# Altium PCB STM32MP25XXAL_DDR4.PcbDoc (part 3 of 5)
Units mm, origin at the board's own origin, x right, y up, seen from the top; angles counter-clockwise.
Board outline 125 x 95 mm, 6 copper layers (Top Layer, Signal Layer 1, Signal Layer 2, Signal Layer 3, Signal Layer 4, Bottom Layer), stack 1.403 mm thick; 220 components, 316 nets, 1103 pads, 939 vias.
Unrouted connection lines stored in the file: 5.
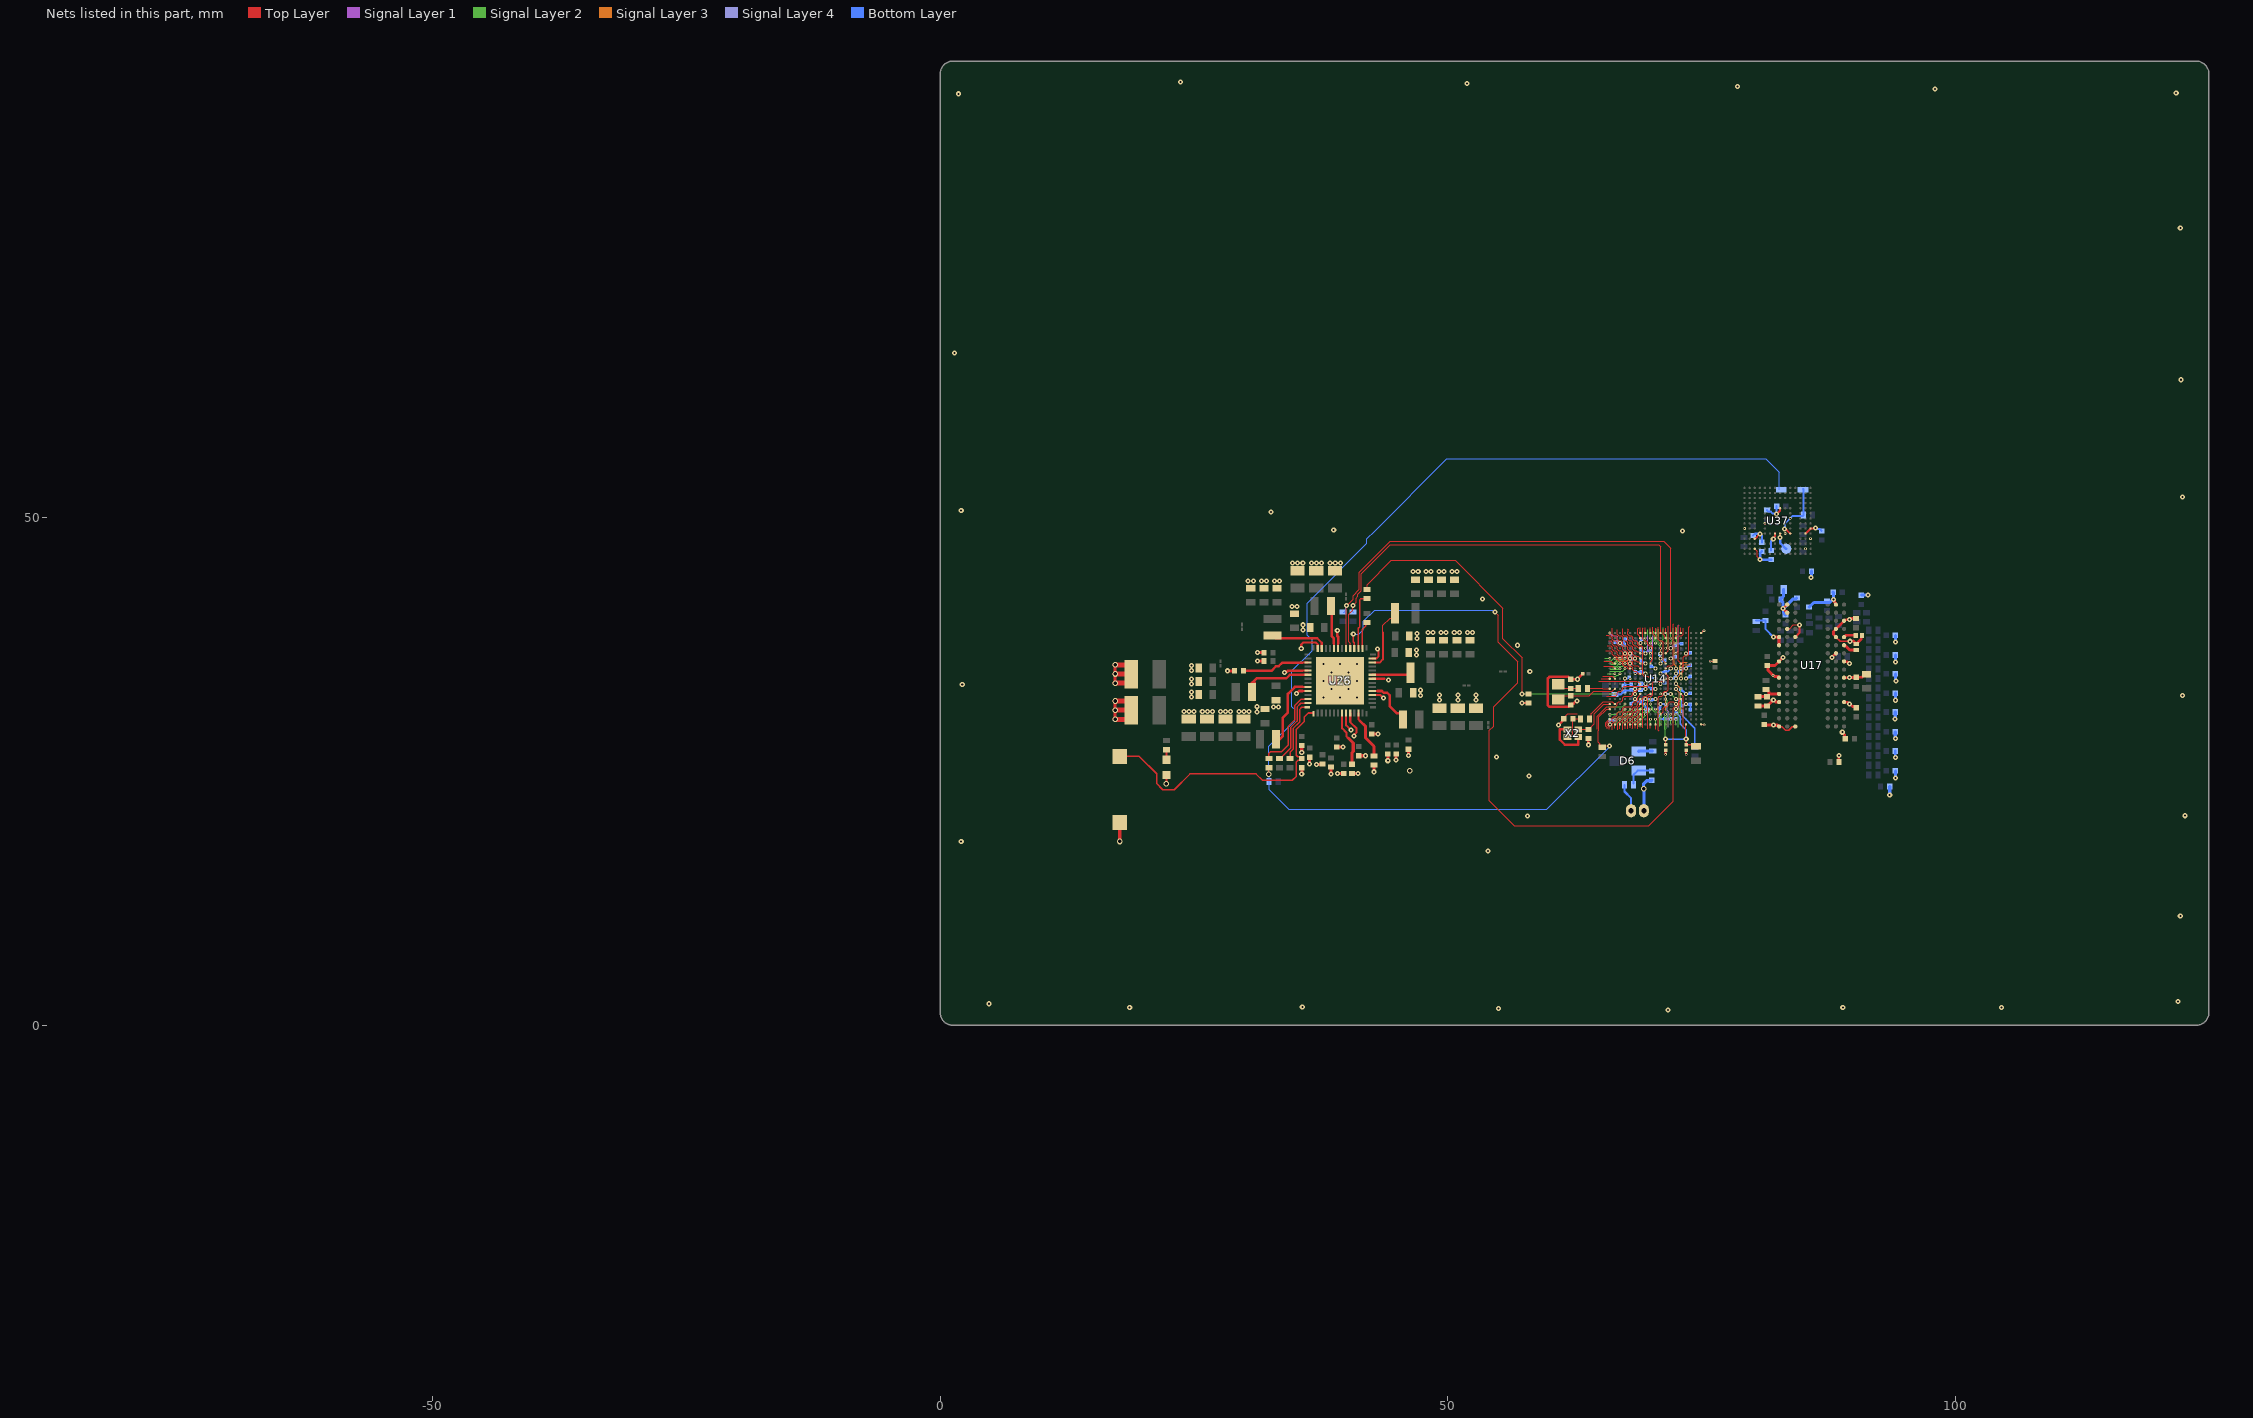
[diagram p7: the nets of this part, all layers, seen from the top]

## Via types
v1: diameter 0.5, hole 0.2, Top Layer to Bottom Layer, 292 vias
v2: diameter 0.26, hole 0.1, Top Layer to Signal Layer 1, 266 vias
v3: diameter 0.26, hole 0.1, Signal Layer 1 to Signal Layer 2, 143 vias
v4: diameter 0.4, hole 0.2, Signal Layer 1 to Signal Layer 4, 101 vias
v5: diameter 0.26, hole 0.1, Signal Layer 4 to Bottom Layer, 81 vias
v6: diameter 0.55, hole 0.35, Top Layer to Bottom Layer, 55 vias
v7: diameter 0.5, hole 0.2, Signal Layer 1 to Signal Layer 4, 1 vias

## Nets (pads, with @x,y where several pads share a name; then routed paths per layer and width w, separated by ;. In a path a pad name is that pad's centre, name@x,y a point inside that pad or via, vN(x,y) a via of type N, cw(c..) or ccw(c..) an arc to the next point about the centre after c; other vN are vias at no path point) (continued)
GND: B2.1 C1.1 C2.1 C3.1 C4.1 C5.1 C9.1 C14.1 C15.1 C16.1 C17.1 C18.2 C19.1 C20.1 C21.1 C22.1 C23.1 C24.1 C26.1 C27.1 C28.1 C29.1 C30.1 C32.1 C33.1 C34.1 C35.1 C36.1 C37.1 C38.1 C39.1 C40.1 C41.1 C42.2 C43.1 C70.1 C79.1 C81.2 C82.1 C86.2 C87.1 C90.1 C91.2 C92.2 C94.1 C104.1 C105.1 C106.1 C112.1 C117.1 C118.1 C128.1 C130.1 C141.2 C142.2 C144.1 C145.1 C146.1 C152.1 C153.1 C154.1 C155.1 C156.1 C157.1 C160.1 C172.1 C175.2 C177.2 C178.1 C179.1 C181.1 C183.1 C184.1 C186.1 C187.1 C188.1 C189.1 C190.2 C191.2 C192.2 C193.1 C194.1 C195.2 C196.1 C197.1 C199.1 C200.1 C201.1 C202.1 C203.2 C204.1 C205.1 C206.1 C207.1 C208.2 C209.1 C210.1 C211.2 C212.1 C213.1 C214.1 C215.1 C217.2 C218.1 C219.1 C220.1 C225.1 C226.1 C234.1 C235.1 C236.1 C237.1 C238.1 C239.1 C240.1 C244.1 C246.1 C248.1 C250.1 C251.1 C252.1 C253.1 C254.1 C255.1 C256.1 C257.1 C258.1 C259.1 C260.1 C261.1 C265.1 C266.1 C283.1 C284.2 C287.1 C289.1 C299.1 C300.1 C304.2 C306.2 C307.2 CN12.2 LD11.2 R57.1 R112.1 R113.1 R118.1 R176.1 R179.1 U14.A1 U14.A19 U14.C3 U14.C7 U14.D13 U14.E8 U14.E16 U14.F6 U14.F11 U14.F13 U14.G8 U14.G11 U14.H10 U14.H13 U14.H16 U14.J6 U14.J8 U14.J11 U14.J14 U14.K4 U14.K5 U14.K10 U14.K13 U14.K16 U14.L8 U14.L11 U14.M6 U14.M10 U14.N11 U14.N13 U14.N16 U14.P6 U14.P8 U14.P10 U14.P14 U14.R11 U14.R16 U14.R18 U14.U1 U14.W1 U14.W19 U17.A2 U17.A8 U17.B2 U17.C9 U17.D2 U17.D8 U17.E1 U17.E3 U17.E8 U17.F1 U17.G8 U17.H1 U17.H9 U17.K1 U17.K9 U17.N1 U17.N9 U17.T1 U17.T3 U26.9 U26.10 U26.18 U26.22 U26.27 U26.36 U26.41 U26.47 U26.52 U26.57 U37.A6 U37.C4 U37.E7 U37.G5 U37.H10 U37.J5 U37.K8 U37.N2 U37.N5 U37.P4 U37.P6 X2.2 X2.4 | length 159.1
  Top Layer w0.075: v2@75.225,38.9 v2@75.275,38.9 ; R112.1@76.35,35.875 76.4,35.875 R112.1@76.425,35.85
  Top Layer w0.09: v2(85.25,46.95) 85.25,46.948 U37.N2@85.251,46.947
  Top Layer w0.1: v1@60.815,29.688 v1(60.901,29.602) ; C92.2@61.431,30.192 61.431,30.294 61.836,30.7 62.761,30.7 ; v1@62.677,34.095 v1@62.709,34.095 ; U14.W19@74.975,29.65 v2@75.3,29.65 ; U14.A19@74.975,38.65 v2@75.225,38.9 ; v2(75.87,35.875) R112.1@76.35,35.875 ; U17.D2@83.45,39.05 83.492,39.092 83.703,39.092 84.06,39.45 v1(84.65,39.45)
  Top Layer w0.15: v2(79.25,48.95) v2(79.25,48.95) U37.A6@79.251,48.947 ; U17.T1@82.65,29.45 82.675,29.425 82.945,29.425 83.295,29.075 83.605,29.075 83.955,29.425 84.225,29.425 U17.T3@84.25,29.45 ; v2(85.75,47.95) 85.75,47.948 U37.P4@85.751,47.947
  Top Layer w0.18: U17.E8@88.25,38.25 88.66,37.84 89.212,37.84 89.217,37.835 v1(89.65,37.835) 89.665,37.85 89.951,37.85
  Top Layer w0.2: v6@22.284,23.784 LD11.2@22.284,24.661 ; U26.27@42.568,36.139 42.977,36.139 43.168,36.33 43.168,37.049 v1@43.214,37.095 ; v1(43.068,37.069) v1@43.125,37.012 ; v1(57.325,31.75) 57.925,31.75 C33.1@57.95,31.725 ; v2(71.475,26.7) C214.1@71.475,27.1 ; v2(73.5,26.7) C260.1@73.5,27.1 ; U37.C4@80.25,47.95 80.256,47.956 80.291,47.956 v1(80.75,48.415) ; v2(81.25,49.45) v2(81.25,49.45) U37.E7@81.251,49.447 ; v1(82.076,47.922) 82.076,48.01 82.251,48.185 U37.G5@82.251,48.447 ; v1(82.401,50.372) 82.751,50.722 U37.H10@82.751,50.947 ; v2(83.25,48.45) 83.251,48.449 U37.J5@83.251,48.447 ; v2(83.75,49.95) v2(83.75,49.95) U37.K8@83.751,49.947 ; U17.E3@84.253,38.25 84.663,38.661 84.663,39.437 v1(84.65,39.45) ; U37.N5@85.251,48.447 85.751,48.947 85.76,48.956 86.206,48.956 v1(86.225,48.975)
  Top Layer w0.21: v1(35.573,37.114) 35.573,37.514 35.778,37.719 37.007,37.719 37.198,37.528 U26.41@37.198,37.109 ; 35.673,32.939 U26.52@36.228,32.939 ; 35.673,34.939 U26.47@36.228,34.939 ; U26.36@39.198,37.109 39.198,37.664 ; U26.9@39.998,30.769 39.998,29.559 v1(40.466,29.091) ; U26.10@40.398,30.769 40.398,29.873 41.033,29.238 41.033,28.859 40.768,28.595 v1(40.768,28.516) ; U26.18@42.568,32.539 43.37,32.539 v1(43.67,32.239) ; U26.22@42.568,34.139 43.123,34.139
  Top Layer w0.25: v1(33.906,34.764) 33.954,34.812 34.155,34.812 34.282,34.939 35.673,34.939 ; v1(35.086,32.701) 35.119,32.701 35.357,32.939 35.673,32.939 ; v1(39.123,38.914) 39.123,38.353 39.198,38.278 39.198,37.664 ; 43.123,34.139 43.728,34.139 ; v1@43.655,32.239 v1(43.67,32.239) ; v1(60.901,29.602) 61.301,30.001 61.301,30.062 C92.2@61.431,30.192 ; X2.2@61.806,29.156 61.039,29.156 61.039,28.159 61.559,27.639 62.856,27.639 X2.4@62.856,28.406 ; v1@62.668,31.972 62.396,31.7 62.242,31.7 C86.2@62.112,31.57 62.087,31.57 61.888,31.37 60.023,31.37 59.877,31.517 59.877,34.174 60.023,34.32 61.887,34.32 C81.2@62.112,34.095 62.677,34.095 62.706,34.124 62.799,34.124 C201.1@63.325,34.65 C201.1@63.35,34.675 ; v1(63.865,27.639) C90.1@63.865,28.256
  Top Layer w0.28: v1(82.1,38.25) U17.E1@82.65,38.25 U17.F1@82.65,37.45 ; v2@82.129,34.45 82.229,34.35 82.536,34.35 82.636,34.25 U17.K1@82.65,34.25 ; U17.B2@83.45,40.65 v1(83.05,41.05) U17.A2@83.45,41.45 ; v1@87.825,36.225 U17.G8@88.25,36.65 ; v1@88.1,41.801 88.1,41.671 U17.A8@88.19,41.581 ; U17.E8@88.26,38.26 88.01,38.51 88.01,38.81 U17.D8@88.25,39.05 U17.C9@89.05,39.85 89.088,39.85 89.196,39.958 89.512,39.958 v1@89.554,40 ; C82.1@88.535,25.945 v1@88.535,26.59 ; U17.N9@89.05,31.85 89.077,31.823 89.392,31.823 v1@89.54,31.675 ; U17.K9@89.05,34.25 v1(89.6,34.25) ; U17.H9@89.05,35.85 89.077,35.823 89.353,35.823 89.536,35.64 v1(89.596,35.64) ; v1(89.6,31.675) 89.609,31.675 89.874,31.41 90.125,31.41 C252.1@90.24,31.295 ; v1(89.6,40) 89.66,40 89.745,40.085 C178.1@90.24,40.085 ; v1@89.638,34.212 v1(89.6,34.25) ; 89.951,37.85 90.15,37.651 90.15,37.635 90.21,37.575 90.26,37.575 90.31,37.575 90.37,37.635 90.37,37.685 90.75,38.065 90.75,38.365 R113.1@90.81,38.425 ; C112.1@91.27,34.605 91.145,34.605 90.835,34.295 C181.1@90.24,34.295 90.218,34.272 89.622,34.272 v1(89.6,34.25)
  Top Layer w0.3: v6@17.245,30.151 v6@17.245,31.951 ; v6@17.245,33.713 v6@17.245,35.513 ; B2.1@17.693,19.993 17.693,18.119 v6(17.698,18.114) ; v1(28.293,34.929) C43.1@28.953,34.929 ; v1(31.283,35.889) C40.1@31.893,35.889 ; v1(31.283,36.714) C39.1@31.893,36.714 ; v1@35.623,26.949 C217.2@35.623,27.559 ; v1@35.625,24.719 C155.1@35.625,25.324 ; v1(36.398,25.749) C154.1@36.398,26.354 ; v1(37.063,25.689) C142.2@37.673,25.689 ; v1@38.498,24.829 C141.2@38.498,25.439 ; C153.1@39.073,27.409 v1(39.683,27.409) ; v1(39.138,24.819) C91.2@39.748,24.819 ; C208.2@40.573,24.819 v1(41.183,24.819) ; C209.1@41.248,26.559 v1(41.883,26.559) ; C156.1@42.523,28.709 v1(43.133,28.709) ; v1(42.748,24.979) R57.1@42.748,25.639 ; v1(44.098,26.069) C189.1@44.098,26.729 ; v1(44.923,26.129) C188.1@44.923,26.729 C188.1@44.923,26.789 ; v1(46.143,26.599) 46.146,26.601 46.146,27.201 C190.2@46.148,27.204 ; R118.1@80.58,31.475 C94.1@81.45,31.475 81.555,31.58 81.603,31.58 v1(82.078,32.054) ; C104.1@81.12,29.585 81.135,29.6 v1(82.11,29.6) 82.148,29.562 82.506,29.562 82.618,29.45 U17.T1@82.65,29.45 ; v1(82.078,32.054) 82.132,32.055 82.314,31.873 82.627,31.873 U17.N1@82.65,31.85 ; v2@82.08,34.46 81.558,34.982 81.558,35.357 81.46,35.455 82.255,35.455 U17.H1@82.65,35.85 v1(83.05,36.25) ; v1(88,41.955) 88,41.901 v1@88.1,41.801 ; U17.A8@88.19,41.581 88.19,41.542 88.25,41.482 U17.A8@88.25,41.45 ; v1(88.875,28.875) 88.875,28.871 89.095,28.651 89.095,28.455 89.175,28.375 C106.1@89.275,28.375
  Top Layer w0.5: v6@17.251,30.145 C18.2@18.834,30.145 ; v6@17.251,31.045 C18.2@18.834,31.045 ; v6@17.251,31.957 C18.2@18.834,31.957 ; v6@17.251,33.707 C42.2@18.834,33.707 ; v6@17.251,34.607 C42.2@18.834,34.607 ; v6@17.251,35.519 C42.2@18.834,35.519
  Signal Layer 1 w0.075: v2(65.975,38.65) 66.225,38.4 66.619,38.4 66.726,38.293 66.726,37.897 66.973,37.65 v4(66.975,37.65) ; v4(71.975,37.15) v4@71.974,37.296
  Signal Layer 1 w0.1: v2@70.975,31.521 v4(70.975,31.65)
  Signal Layer 2 w0.1: v4(71.974,32.65) v4(72.475,32.15)
  Bottom Layer w0.1: C235.1@67.325,33.45 C235.1@67.375,33.5 C235.1@67.45,33.575 ; C235.1@67.45,33.475 C235.1@67.45,33.575 ; C236.1@67.875,34.275 67.875,34.27 67.755,34.15 v2(67.475,34.15) 67.45,34.125 C235.1@67.45,33.575 ; C244.1@68.07,33.605 67.48,33.605 C235.1@67.45,33.575 ; C234.1@68.075,31.7 68.195,31.82 68.195,31.875 68.258,31.938 68.3,31.938 68.47,32.108 v5@68.47,32.15 ; C244.1@68.075,33.6 68.195,33.48 68.444,33.231 68.444,33.181 v5(68.475,33.15) 68.475,33.162 68.613,33.3 68.613,33.305 68.795,33.487 68.795,33.5 68.945,33.65 68.975,33.65 C225.1@68.995,33.65 C225.1@69,33.65 ; C240.1@68.075,35.95 C240.1@68.075,36.08 ; v4(72.475,32.15) 72.482,32.15 72.607,32.025 72.925,32.025 72.925,32 73.05,31.875 C251.1@73.05,31.5 ; C251.1@72.975,31.5 C251.1@73.05,31.5 ; C251.1@73.05,31.475 C251.1@73.05,31.5 ; v4(73.475,31.65) 73.325,31.5 C251.1@73.05,31.5 ; R176.1@80.35,39.875 R176.1@80.37,39.895
  Bottom Layer w0.2: 65.971,29.854 65.971,29.678 65.974,29.675 v5@65.975,29.675 ; C215.1@66.525,37.75 C215.1@66.525,37.745 66.6,37.67 66.605,37.67 66.625,37.65 v4(66.975,37.65) 66.991,37.65 67.105,37.536 67.389,37.536 C237.1@67.396,37.529 ; C237.1@67.38,37.5 67.38,37.95 C220.1@67.48,38.05 ; C240.1@68.045,36.05 C17.1@68.045,36.6 ; C240.1@68.05,36.05 68.05,36.055 68.075,36.08 68.12,36.125 68.125,36.125 68.15,36.15 v4(68.475,36.15) v5@68.491,36.15 ; C240.1@68.05,36.08 C240.1@68.055,36.075 ; v5@68.475,32.143 v5(68.475,32.15) ; v5@68.478,32.146 68.75,31.875 69.157,31.875 69.432,32.15 v5@69.45,32.15 ; C197.1@68.5,34.825 C307.2@69.05,34.825 69.125,34.75 69.359,34.75 69.459,34.65 v4(69.475,34.65) ; C197.1@68.5,34.85 C197.1@68.529,34.879 ; C225.1@68.95,33.675 C225.1@68.975,33.65 ; v4(68.975,37.65) 68.975,37.93 C16.1@69.1,38.055 ; C225.1@69,33.65 v4(69.475,33.65) 69.82,33.305 69.92,33.305 70.05,33.175 70.475,33.175 v5@70.525,33.125 ; C212.1@69.025,37.025 C212.1@69.05,37.025 C212.1@69.125,36.95 ; C300.1@69.05,31.875 69.47,31.455 69.47,31.205 C87.1@69.625,31.05 ; C205.1@69.075,35.925 69.075,35.9 69.125,35.85 69.168,35.85 69.278,35.74 69.369,35.74 69.459,35.65 v5@69.468,35.65 ; C212.1@69.125,36.949 69.242,36.832 69.3,36.832 69.475,36.657 v5(69.475,36.65) 69.775,36.95 69.975,36.95 C219.1@70.05,37.025 ; v4(69.475,32.15) 70,32.15 C195.2@70.075,32.075 ; C195.2@70.05,32.075 C195.2@70.075,32.075 ; C196.1@70.05,34.275 70.108,34.217 70.392,34.217 70.459,34.15 v5(70.475,34.15) ; C213.1@70.05,35.375 70.116,35.309 70.316,35.309 v5(70.475,35.15) ; C195.2@70.125,32.025 C195.2@70.075,32.075 ; v5@70.475,32.15 70.432,32.15 70.357,32.075 C195.2@70.075,32.075 ; C2.1@70.85,31.225 70.825,31.2 70.825,30.312 70.942,30.195 C253.1@71.4,30.195 71.402,30.197 71.948,30.197 C246.1@71.95,30.195 C15.1@72.5,30.195 ; C2.1@70.875,31.25 70.975,31.35 v4(70.975,31.65) 71.328,31.65 71.348,31.63 71.495,31.63 C4.1@71.55,31.575 ; C210.1@70.875,36.575 70.933,36.517 70.933,36.208 70.975,36.166 v4(70.975,36.15) ; v4(70.975,33.65) 70.991,33.65 71.048,33.707 71.352,33.707 C3.1@71.4,33.755 ; v5@70.975,35.675 70.984,35.675 70.986,35.678 70.986,35.686 71.18,35.88 71.325,35.88 C299.1@71.4,35.955 ; v5(70.976,34.65) 70.983,34.65 71.134,34.8 71.425,34.8 71.466,34.841 71.666,34.841 v4(71.975,35.15) ; C1.1@71.405,32.65 v4(71.974,32.65) ; v4(71.975,34.15) 72.325,34.15 72.433,34.258 72.433,34.592 72.475,34.634 v4(72.475,34.65) 72.486,34.661 72.605,34.661 72.765,34.821 72.765,34.89 72.95,35.075 73.012,35.137 73.446,35.137 v5@73.447,35.139 ; v4(71.975,36.15) 71.991,36.15 72.091,36.25 72.325,36.25 C191.2@72.4,36.325 C191.2@72.4,36.35 ; v4(71.975,37.15) 72.159,37.334 72.309,37.334 C287.1@72.4,37.425 ; C287.1@72.375,37.425 C287.1@72.4,37.425 ; C283.1@72.95,33.125 73.135,32.94 73.154,32.94 73.194,32.9 73.2,32.9 73.439,32.661 73.447,32.661 73.475,32.634 v5@73.475,32.625 ; C238.1@73.07,37.605 72.58,37.605 C287.1@72.4,37.425 ; v4(73.475,31.65) 73.5,31.625 C192.2@73.9,31.625 ; v4(73.475,32.65) 73.825,32.65 C306.2@73.9,32.725 ; v4(73.475,34.15) 73.491,34.15 73.591,34.25 73.775,34.25 C211.2@73.9,34.375 ; v5(73.475,35.15) 73.486,35.161 73.486,35.186 73.701,35.4 73.825,35.4 C175.2@73.9,35.475 ; v4(73.475,36.65) 73.875,36.65 C304.2@73.925,36.7 ; C284.2@73.925,31.025 73.9,31.05 C284.2@73.9,31.075 C192.2@73.9,31.625 ; C192.2@73.925,31.625 C192.2@73.9,31.625 ; C118.1@80.096,48.263 80.261,48.428 80.761,48.428 80.946,48.243 C79.1@80.946,47.588 ; R176.1@80.37,39.895 C255.1@81.31,39.895 ; C255.1@81.325,39.85 81.325,39.025 v1(82.1,38.25) ; C9.1@81.451,50.763 81.606,50.608 81.845,50.608 82.044,50.409 82.366,50.409 82.411,50.363 C117.1@82.411,51.148 ; C130.1@81.864,46.788 81.864,47.691 v1@82.086,47.913 ; v1@86.25,48.975 86.32,48.905 86.645,48.905 C128.1@86.85,48.7
  Bottom Layer w0.28: C248.1@65.95,30.05 C250.1@66.5,30.05 ; C218.1@82.75,41.91 82.75,41.935 82.75,41.96 82.865,42.075 82.915,42.075 83.094,42.254 83.094,42.939 C172.1@83.11,42.955 ; v1@85.81,44.085 v1@85.83,44.105 ; v1(85.81,44.1) 85.83,44.12 85.83,44.73 C70.1@85.85,44.75 ; v1@94.09,26.37 94.095,26.375 94.095,27.02 C266.1@94.1,27.025
  Bottom Layer w0.3: CN12.2@69.325,20.734 69.325,23.3 v6(69.3,23.325) 69.31,23.335 69.31,23.802 69.602,24.094 70.06,24.094 C14.1@70.117,24.151 ; C218.1@82.75,41.91 82.855,41.805 82.874,41.805 83.05,41.629 v1(83.05,41.05) ; C160.1@83.29,40.425 83.265,40.425 83.16,40.53 83.16,40.555 83.088,40.627 83.088,41.012 v1(83.05,41.05) ; C254.1@84.35,42.1 84.35,42.05 84.29,41.99 83.99,41.99 v1(83.05,41.05) ; C259.1@85.6,41.205 85.625,41.205 86.075,41.655 87.646,41.655 87.946,41.955 v1(88,41.955) 88,42.645 C179.1@87.98,42.665 ; C258.1@90.75,42.375 v1@91.41,42.375 ; v1@93.55,22.705 C145.1@93.55,23.525 ; v1@94.09,30.235 94.095,30.24 94.095,30.87 C239.1@94.1,30.875 ; v1@94.095,28.26 C257.1@94.095,28.92 ; C265.1@94.1,25.075 94.11,25.065 94.11,24.395 v1@94.12,24.385 ; v1@94.1,32.055 C226.1@94.1,32.725 ; C144.1@94.1,34.625 94.12,34.605 94.12,33.945 v1@94.14,33.925 ; v1@94.1,35.785 C256.1@94.1,36.475 ; v1@94.1,37.765 C146.1@94.1,38.425
  other v1: 71.7,1.5 55,1.675 18.675,1.75 88.925,1.75 104.55,1.75 35.675,1.825 4.825,2.125 121.95,2.35 122.175,10.75 53.961,17.189 2.075,18.1 57.873,20.639 122.65,20.65 93.55,22.675 94.125,24.35 58.023,24.564 35.62,24.749 38.498,24.779 94.125,26.375 54.8,26.444 88.54,26.595 35.623,26.899 94.1,28.25 94.075,30.175 31.223,30.889 24.022,30.937 24.523,30.937 25.024,30.937 25.822,30.937 26.323,30.937 26.824,30.937 27.622,30.937 28.123,30.937 28.624,30.937 29.422,30.937 29.923,30.937 30.424,30.937 32.822,31.341 33.323,31.341 31.223,31.389 62.725,31.972 94.1,32.025 49.202,32.039 51.002,32.039 52.802,32.039 37.748,32.289 39.398,32.289 41.048,32.289 24.748,32.339 47.318,32.514 122.4,32.5 49.202,32.54 51.002,32.54 52.802,32.54 24.748,32.839 47.318,33.014 38.573,33.114 40.223,33.114 2.175,33.575 24.748,33.639 37.748,33.939 39.398,33.939 41.048,33.939 94.15,33.925 44.178,34.014 62.78,34.095 24.748,34.139 38.573,34.764 40.223,34.764 58.087,34.852 24.748,34.939 24.748,35.439 37.748,35.589 39.398,35.589 41.048,35.589 94.125,35.775 87.85,36.25 46.948,36.464 46.948,36.964 56.893,37.444 94.1,37.75 46.973,38.114 46.973,38.614 48.048,38.714 48.548,38.714 49.348,38.714 49.848,38.714 50.648,38.714 51.148,38.714 51.948,38.714 52.448,38.714 35.748,38.962 35.748,39.462 34.673,41.262 35.174,41.262 53.433,42.004 91.405,42.375 30.348,43.762 30.849,43.762 31.648,43.762 32.149,43.762 32.948,43.762 33.449,43.762 46.598,44.714 47.098,44.714 47.873,44.714 48.373,44.714 49.148,44.714 49.648,44.714 50.423,44.714 50.923,44.714 34.722,45.564 35.223,45.564 35.724,45.564 36.572,45.564 37.073,45.564 37.574,45.564 38.422,45.564 38.923,45.564 39.424,45.564 73.125,48.7 38.773,48.814 32.573,50.576 2.075,50.725 122.4,52.05 122.25,63.6 1.4,66.25 122.175,78.55 1.8,91.775 121.775,91.85 98,92.25 78.55,92.475 51.9,92.775 23.675,92.925
  other v2: 75.275,29.6 65.975,29.65 65.975,30.65 70.975,31.65 73.475,31.65 74.475,31.65 68.475,32.15 69.475,32.15 70.474,32.149 72.475,32.15 70.974,32.649 71.974,32.65 73.475,32.65 68.475,33.15 70.475,33.15 69.475,33.65 70.975,33.65 67.975,34.15 70.475,34.15 71.975,34.15 73.475,34.15 82.05,34.46 68.475,34.65 69.475,34.65 70.976,34.65 72.475,34.65 70.475,35.15 71.975,35.15 73.475,35.15 69.475,35.65 70.975,35.65 68.475,36.15 70.975,36.15 71.975,36.15 69.475,36.65 73.475,36.65 71.975,37.15 66.975,37.65 68.975,37.65 75.257,38.889
  other v4: 65.975,29.65 68.475,32.15 70.474,32.149 68.475,33.15 70.475,33.15 67.475,34.15 70.475,34.15 70.976,34.65 70.475,35.15 73.475,35.15 69.475,35.65 70.975,35.65 69.475,36.65
  other v5: 65.975,29.65 70.975,31.65 73.475,31.65 69.475,32.15 70.474,32.149 72.475,32.15 71.975,32.65 73.475,32.65 70.475,33.15 69.475,33.65 70.975,33.65 67.475,34.15 71.975,34.15 73.475,34.15 69.475,34.65 72.475,34.65 71.975,35.15 69.475,35.65 70.975,35.65 68.475,36.15 70.975,36.15 71.975,36.15 73.475,36.65 71.975,37.15 66.975,37.65 68.975,37.65
  other v6: 22.285,23.787 46.248,25.084 17.246,30.153 17.246,31.053 17.246,31.953 17.246,33.715 17.246,34.615 17.246,35.515
HSE_IN: C90.2 U14.R1 X2.1 | length 4.8
  Top Layer w0.1: X2.1@62.856,29.156 C90.2@63.89,29.156 ; C90.2@63.865,29.156 C90.2@63.89,29.156 ; U14.R1@65.975,31.65 65.575,31.65 65.372,31.65 64.425,30.703 64.425,29.691 C90.2@63.89,29.156
HSE_OUT: R3.2 U14.R2 | length 3.5
  Top Layer w0.1: R3.2@63.981,30.192 64.162,30.373 64.162,30.721 ; 64.175,30.725 65.35,31.9 66.225,31.9 U14.R2@66.475,31.65
I2C7.SCL: R261.1 U14.A11 U26.33 | length 47.8
  Top Layer w0.1: U26.33@40.398,37.109 40.398,37.639 40.248,37.789 40.248,40.498 40.661,40.911 v1(40.661,41.364) ; v1@40.75,41.375 40.75,41.453 40.984,41.687 40.984,42.084 41.15,42.25 ; 41.146,42.25 41.146,42.475 41.475,42.804 41.475,44.464 44.336,47.325 70.775,47.325 70.975,47.125 U14.A11@70.975,38.65
  Bottom Layer w0.1: v1@40.641,41.364 40.641,40.763 R261.1@40.684,40.72
I2C7.SDA: R260.1 U14.A13 U26.34 | length 49.4
  Top Layer w0.1: U26.34@39.998,37.109 v1@39.998,41.298 ; v1(40.05,41.35) 40.674,41.974 40.674,42.344 41.269,42.938 41.269,44.644 44.325,47.7 71.275,47.7 71.975,47 U14.A13@71.975,38.65
  Bottom Layer w0.1: R260.1@39.709,40.72 39.799,40.72 39.979,40.9 39.979,41.279 v1(40.05,41.35)
JTDI: U14.W3 | length 0.4
  Top Layer w0.075: 66.975,29.225 U14.W3@66.975,29.65
JTDO_TRACESWO: U14.V1 | length 1.2
  Top Layer w0.075: 65.7,29.2 65.7,29.339 65.56,29.478 65.56,29.822 65.803,30.064 65.814,30.064 65.87,30.12 65.945,30.12 U14.V1@65.975,30.15
JTMS_SWCLK: U14.W4 | length 0.4
  Top Layer w0.075: 67.475,29.225 U14.W4@67.475,29.65
JTMS_SWDIO: U14.W2 | length 0.4
  Top Layer w0.075: 66.475,29.25 U14.W2@66.475,29.65
LVDS1_D0N: U14.F1 | length 0.6
  Top Layer w0.075: U14.F1@65.95,36.125 v3(65.975,36.15)
  Signal Layer 2 w0.075: 65.45,36.15 v3(65.975,36.15)
  other v2: 65.975,36.15
LVDS1_D0P: U14.F2 | length 1
  Signal Layer 2 w0.075: 65.575,35.9 66.101,35.9 66.316,36.116 66.441,36.116 v3(66.475,36.15)
  other v2: 66.475,36.15
LVDS1_D1N: U14.F3 | length 1.2
  Signal Layer 2 w0.075: 65.95,35.735 66.413,35.735 66.792,36.115 66.94,36.115 v3(66.975,36.15)
  other v2: 66.975,36.15
LVDS1_D1P: U14.F4 | length 1.7
  Signal Layer 2 w0.075: 66.054,35.565 66.57,35.565 66.726,35.72 66.726,35.753 66.872,35.899 67.087,35.899 67.225,35.899 v3(67.475,36.15)
  other v2: 67.475,36.15
LVDS1_D2N: U14.G3 | length 1
  Signal Layer 2 w0.075: 66.123,35.4 66.639,35.4 66.803,35.564 66.839,35.564 66.925,35.65 v3(66.975,35.65)
  other v2: 66.975,35.65
LVDS1_D2P: U14.G4 | length 1.5
  Signal Layer 2 w0.075: 66.175,35.235 66.707,35.235 66.872,35.399 66.908,35.399 67.226,35.399 v3(67.475,35.649)
  other v2: 67.475,35.649
LVDS1_D3N: U14.J2 | length 0.8
  Signal Layer 2 w0.075: 65.725,34.65 v3(66.475,34.65)
  other v2: 66.475,34.65
LVDS1_D3P: U14.J3 | length 1.3
  Signal Layer 2 w0.075: 65.75,34.4 66.578,34.4 66.678,34.5 66.825,34.5 v3(66.975,34.65)
  other v2: 66.975,34.65
LVDS1_D4N: U14.H3 | length 1
  Signal Layer 2 w0.075: 66.032,35.07 66.845,35.07 66.925,35.15 v3(66.975,35.15)
  other v2: 66.975,35.15
LVDS1_D4P: U14.H4 | length 1.6
  Signal Layer 2 w0.075: 65.968,34.901 67.226,34.901 v3(67.475,35.15)
  other v2: 67.475,35.15
MP257_WAKEUP: U14.P15 U26.32 | length 68.3
  Top Layer w0.075: 72.225,29.275 72.225,31.253 72.372,31.4 72.577,31.4 72.74,31.563 72.74,31.915 U14.P15@72.975,32.15
  Top Layer w0.1: v1(54.649,40.719) 54.961,40.408 54.961,37.743 56.893,35.811 56.893,33.768 54.529,31.404 54.529,29.487 54.098,29.055 54.098,22.132 56.566,19.663 69.813,19.663 72.229,22.079 72.229,29.271
  Top Layer w0.15: v1(40.698,38.539) 40.698,37.792 40.798,37.692 U26.32@40.798,37.109
  Bottom Layer w0.1: v1@40.679,38.54 41.26,38.54 41.679,38.96 41.679,39.798 42.797,40.915 54.442,40.915 54.639,40.717 v1@54.65,40.717
NetB2_2: B2.2 C155.2 U26.1 | length 28.3
  Top Layer w0.15: B2.2@17.693,26.493 19.619,26.493 21.336,24.776 21.336,23.812 21.934,23.214 23.06,23.214 24.611,24.764 31.117,24.764 31.743,24.138 34.697,24.138 35.098,24.539 35.098,25.964 35.245,26.111 35.452,26.111 C155.2@35.625,26.284 35.46,26.449 35.236,26.449 35.086,26.599 35.086,29.147 35.86,29.922 35.86,30.376 36.253,30.769 U26.1@36.798,30.769
NetC14_2: C14.2 D6.2 R66.2 | length 2.9
  Bottom Layer w0.2: R66.2@68.307,23.82 68.307,24.692 68.707,25.092 D6.2@68.826,25.092 70.075,25.092 C14.2@70.117,25.051
NetC15_2: C15.2 C214.2 C260.2 R11.2 U14.T14 U14.U12 U14.W16 | length 11.6
  Top Layer w0.075: C214.2@71.45,27.675 71.475,27.7 v1(71.475,28.2)
  Top Layer w0.09: U14.W16@73.475,29.65 73.475,28.225 v1(73.5,28.2) ; C260.2@73.5,27.8 73.5,27.675 C260.2@73.525,27.65 ; R11.2@74.32,27.45 R11.2@74.525,27.45
  Top Layer w0.15: C260.2@73.5,27.8 v1(73.5,28.2) ; C260.2@73.525,27.65 74.12,27.65 R11.2@74.32,27.45
  Signal Layer 2 w0.075: v1(71.475,28.2) 71.425,28.25 71.425,29.128 71.382,29.171 71.382,30.514 71.475,30.607 v3(71.475,30.65)
  Bottom Layer w0.1: C15.2@72.475,30.775 v4(72.475,31.15)
  Bottom Layer w0.15: v1@71.45,28.2 v1(71.475,28.2) v1(73.5,28.2) ; C15.2@72.5,30.745 72.6,30.645 72.678,30.645 72.918,30.405 72.918,29.682 73.525,29.075 v1@73.525,28.2
  other v2: 71.475,30.65 72.475,31.15
  other v5: 72.475,31.15
NetC43_2: C43.2 U26.45 | length 6.7
  Top Layer w0.21: 35.673,35.739 U26.45@36.228,35.739
  Top Layer w0.25: C43.2@29.913,34.929 32.629,34.929 33.074,35.374 33.349,35.374 33.714,35.739 35.673,35.739
NetC79_2: C79.2 C130.2 U37.C2 | length 3.3
  Top Layer w0.09: U37.C2@80.251,46.947 80.253,46.947 80.492,46.708 80.492,46.158 v1(80.775,45.875)
  Bottom Layer w0.25: C79.2@80.946,46.688 80.941,46.688 80.811,46.558 80.811,45.911 v1(80.775,45.875) 80.782,45.882 81.857,45.882 C130.2@81.864,45.888
NetC81_1: C81.1 R64.2 X1.1 | length 2.1
  Top Layer w0.1: X1.1@60.886,33.595 61.286,33.195 C81.1@62.112,33.195 R64.2@62.862,33.195
NetC92_1: C92.1 R3.1 X2.3 | length 2.9
  Top Layer w0.1: X2.3@61.806,28.406 62.033,28.633 62.265,28.633 62.331,28.699 C92.1@62.331,30.192 R3.1@63.081,30.192
NetC94_2: C94.2 R116.2 R118.2 U17.M1 | length 2.8
  Top Layer w0.3: R118.2@80.58,32.375 C94.2@81.45,32.375 81.68,32.605 81.68,32.755 81.55,32.885 81.55,32.98 81.445,33.085 R116.2@81.35,33.085 ; 81.75,32.65 U17.M1@82.65,32.65
NetC208_1: C208.1 U26.8 | length 5.4
  Top Layer w0.21: U26.8@39.598,30.769 39.598,29.273 40.023,28.848 40.023,28.484 40.196,28.311
  Top Layer w0.3: 40.196,28.311 40.698,27.809 40.698,26.982 40.573,26.856 C208.1@40.573,25.844
NetC225_2: C225.2 U14.M8 | length 0.5
  Bottom Layer w0.2: C225.2@69,33.025 69.125,33.15 v5(69.475,33.15)
  other v2: 69.475,33.15
  other v4: 69.475,33.15
NetC235_2: C235.2 C244.2 R267.1 U14.N6 | length 2.4
  Bottom Layer w0.2: R267.1@66.5,32.6 67.075,32.6 67.225,32.75 67.225,32.8 67.325,32.9 C235.2@67.375,32.9 67.475,33 68.015,33 C244.2@68.07,33.055 ; C244.2@68.075,33.05 v5(68.475,32.65)
  other v2: 68.475,32.65
  other v4: 68.475,32.65
NetC251_2: C251.2 R286.2 U14.R14 U14.U11 | length 7.6
  Top Layer w0.075: U14.U11@70.95,30.6 71.224,30.874 71.224,31.231 71.391,31.397 71.575,31.397 71.725,31.547 71.725,31.753 71.872,31.899 72.226,31.899 v4(72.475,31.65)
  Bottom Layer w0.1: v4(72.475,31.65) 72.743,31.382 72.743,31.232 C251.2@73.05,30.925
  Bottom Layer w0.15: C251.2@73.05,30.925 73.15,30.825 73.15,30.475 74.35,29.275 R286.2@74.35,27.35
  other v2: 72.475,31.65
  other v5: 72.475,31.65
NetCN12_1: CN12.1 R66.1 | length 3.2
  Bottom Layer w0.2: R66.1@67.416,23.699 67.416,23.033 68.074,22.375 CN12.1@68.074,20.815
NetD6_1: D6.1 R67.1 | length 1.4
  Bottom Layer w0.3: D6.1@68.826,26.992 68.874,27.041 R67.1@70.199,27.041
NetD7_1: D7.1 R248.1 U37.K5 | length 6
  Top Layer w0.2: v1@83.201,48.997 U37.K5@83.751,48.447
  Bottom Layer w0.2: v1@83.201,48.997 83.213,49.009 83.213,49.413 84,50.2 85.025,50.2 R248.1@85.075,50.25 ; D7.1@85.031,52.846 85.043,52.834 R248.1@85.043,50.263
  other v1: 83.2,48.915
NetL1_1: L1.1 U26.37 | length 4.2
  Top Layer w0.21: U26.37@38.798,37.109 38.798,37.664
  Top Layer w0.25: L1.1@38.598,41.274 38.598,38.312 38.798,38.112 38.798,37.664
NetL2_1: L2.1 U26.26 | length 6
  Top Layer w0.09: 43.623,38.699 43.623,39.399 44.331,40.107 44.458,40.107 44.813,40.462 L2.1@44.813,40.589
  Top Layer w0.2: U26.26@42.815,35.739 43.298,35.739 43.623,36.064 43.623,38.699
NetL3_1: L3.1 U26.40 | length 5.9
  Top Layer w0.15: L3.1@32.596,38.301 L3.1@32.748,38.149
  Top Layer w0.21: L3.1@32.748,38.414 33.033,38.129 34.808,38.129 ; 34.808,38.129 37.163,38.129 37.598,37.694 U26.40@37.598,37.109
NetL4_1: L4.1 U26.23 | length 3.8
  Top Layer w0.15: L4.1@46.258,34.024 L4.1@46.258,34.539
  Top Layer w0.21: U26.23@42.568,34.539 43.123,34.539
  Top Layer w0.25: 43.123,34.539 45.898,34.539
NetL5_1: L5.1 U26.48 | length 7.2
  Top Layer w0.15: L5.1@30.516,32.587 L5.1@30.768,32.839 ; L5.1@30.988,32.724 L5.1@30.988,33.239
  Top Layer w0.21: 35.673,34.539 U26.48@36.228,34.539
  Top Layer w0.25: 30.723,33.739 31.173,34.189 34.098,34.189 34.448,34.539 35.673,34.539 ; L5.1@30.988,33.239 30.988,33.754
NetL6_1: L6.1 U26.19 | length 4.9
  Top Layer w0.21: U26.19@42.568,32.939 43.123,32.939
  Top Layer w0.25: 43.123,32.939 43.521,32.939 43.696,32.764 44.048,32.764 44.273,32.539 44.273,31.464 44.969,30.768 45.323,30.768 45.328,30.763 L6.1@45.328,30.164
NetL7_1: L7.1 U26.51 | length 7.4
  Top Layer w0.21: 35.673,33.339 U26.51@36.228,33.339
  Top Layer w0.25: L7.1@33.323,28.564 L7.1@33.323,28.808 ; L7.1@33.373,28.089 33.773,28.489 33.773,30.323 34.248,30.798 34.248,32.642 34.945,33.339 35.673,33.339
NetLD11_1: LD11.1 R210.2 | length 1
  Top Layer w0.2: LD11.1@22.284,26.161 R210.2@22.284,27.154
NetR2_2: R2.2 U26.56 | length 6.1
  Top Layer w0.15: R2.2@34.478,26.284 34.478,26.899 34.773,27.194 34.773,29.23 35.41,29.867 35.41,31.124 35.625,31.339 U26.56@36.153,31.339
NetR46_2: R46.2 U26.30 | length 2.8
  Top Layer w0.15: U26.30@41.598,37.109 41.598,39.009 41.93,39.341 41.93,39.569 R46.2@42.048,39.687
NetR57_2: R57.2 U26.12 | length 4.9
  Top Layer w0.21: U26.12@41.198,30.769 41.198,30.155 41.368,29.984
  Top Layer w0.3: 41.368,29.984 41.923,29.43 41.923,28.313 42.748,27.488 R57.2@42.748,26.539
NetR59_2: R59.2 U26.54 | length 8.5
  Top Layer w0.15: R59.2@32.378,26.284 32.378,26.779 32.548,26.949 33.634,26.949 34.273,27.588 34.273,29.437 34.91,30.074 34.91,31.474 35.575,32.139 U26.54@36.228,32.139
NetR60_2: R60.2 U26.55 | length 7.1
  Top Layer w0.15: R60.2@33.428,26.284 33.502,26.284 34.523,27.305 34.523,29.333 35.16,29.971 35.16,31.371 35.529,31.739 U26.55@36.228,31.739
NetR81_2: R81.2 U26.31 | length 5.7
  Top Layer w0.15: U26.31@41.198,37.109 41.198,39.112 41.348,39.262 41.348,41.949 41.436,42.037 R81.2@42.061,42.037
NetR113_2: R113.2 U17.E9 | length 1.2
  Top Layer w0.28: U17.E9@89.05,38.25 89.088,38.25 89.263,38.425 R113.2@90.21,38.425
NetR179_2: R179.2 U17.F9 | length 1.4
  Top Layer w0.3: U17.F9@89.05,37.45 89.073,37.427 89.166,37.427 89.618,36.975 R179.2@90.26,36.975
NetTP21_1: TP21.1 U37.H5 | length 1.7
  Top Layer w0.15: v1(82.751,48.047) U37.H5@82.751,48.447
  Bottom Layer w0.25: v1@82.761,48.038 82.761,47.539 TP21.1@83.352,46.948
NJTRST: U14.V2 | length 0.6
  Signal Layer 2 w0.075: v3(66.475,30.15) 66.509,30.116 66.509,29.562
  other v2: 66.475,30.15
NRST: C33.2 R81.1 U14.N2 | length 35.9
  Top Layer w0.1: R81.1@42.061,42.937 42.061,43.412 44.463,45.814 50.736,45.814 55.439,41.111 55.439,38.088 57.328,36.199 57.328,32.653 v1(57.325,32.65) 57.95,32.65 C33.2@57.975,32.625
  Signal Layer 2 w0.075: v1(57.325,32.65) v3(66.475,32.65)
  other v2: 66.475,32.65
NRSTC1MS: D7.2 R27.1 R59.1 R272.1 U14.T1 | length 118.3
  Top Layer w0.075: R27.1@65.213,27.513 65.106,27.513 65.001,27.617 65.001,27.724 64.85,27.875 64.85,29.037 64.907,29.094 64.907,30.382 65.675,31.15 U14.T1@65.975,31.15
  Top Layer w0.1: R59.1@32.378,25.384 32.373,25.379 32.373,24.764 v6@32.388,24.749 ; R27.1@65.225,27.525 v1(65.95,27.525)
  Bottom Layer w0.1: R272.1@32.4,24 32.4,23.2 34.325,21.275 59.784,21.275 65.95,27.441 v1(65.95,27.525) ; R272.1@32.404,24.019 32.404,24.732 32.389,24.747 32.389,27.505 34.91,30.026 34.91,31.138 34.66,31.388 34.66,34.935 36.647,36.922 36.647,37.978 36.175,38.45 36.175,41.6 42.05,47.475 42.05,47.925 42.856,48.731 42.856,48.738 49.918,55.8 81.36,55.8 82.685,54.475 D7.2@82.685,52.788
  other v6: 32.388,24.739
OSC32_IN: C86.1 U14.M2 X1.2 | length 6
  Top Layer w0.1: X1.2@60.886,32.095 61.26,32.47 C86.1@62.112,32.47 63.97,32.47 64.4,32.9 66.225,32.9 U14.M2@66.475,33.15
OSC32_OUT: R64.1 U14.M1 | length 2.2
  Top Layer w0.1: R64.1@63.762,33.195 65.23,33.195 65.275,33.15 U14.M1@65.975,33.15
PA1: U14.N15 | length 3.5
  Top Layer w0.075: U14.N15@72.975,32.65 73.225,32.4 73.225,29.249
PA2: U14.N12 | length 1.6
  Signal Layer 3 w0.075: 71.45,31.075 71.475,31.1 v2(71.475,32.65)
  other v4: 71.475,32.65
PA3: U14.R12 | length 2.4
  Signal Layer 1 w0.075: v2(71.475,31.65) 71.509,31.616 71.509,31.491 71.625,31.375 71.625,31.048 71.725,30.948 71.725,29.373
PA4: U14.P12 | length 3.1
  Signal Layer 2 w0.075: v3(71.475,32.15) 71.636,31.989 71.636,30.842 71.724,30.753 71.724,30.547 71.539,30.361 71.539,29.236
  other v2: 71.475,32.15
PA5: U14.J12 | length 6.4
  Top Layer w0.075: 70.775,29.025 70.725,29.074 70.725,32.276 70.849,32.399 71.077,32.399 71.225,32.547 71.225,32.753 71.373,32.901 71.578,32.901 71.724,33.047 71.724,33.249 ; U14.J12@71.475,34.65 71.725,34.4 71.725,33.425 ; 71.724,33.25 71.724,33.4
PA6: U14.M14 | length 2.4
  Signal Layer 3 w0.075: v3(72.475,33.15) 72.475,33.127 72.813,32.789 72.813,30.845
  other v2: 72.475,33.15
  other v4: 72.475,33.15
PA7: U14.K15 | length 2.1
  Signal Layer 3 w0.075: v3(72.975,34.15) 72.975,34.222 73.11,34.356 73.11,35.309 73.326,35.525 73.925,35.525
  other v2: 72.975,34.15
  other v4: 72.975,34.15
PA8: U14.K9 | length 6.4
  Top Layer w0.075: 67.7,39.05 67.775,38.975 67.775,38.803 67.726,38.753 67.726,38.547 67.873,38.399 68.078,38.399 68.224,38.253 68.224,38.048 68.373,37.9 68.578,37.9 68.726,37.752 68.726,37.547 68.875,37.398 69.07,37.398 69.226,37.242 69.226,34.547 69.372,34.401 69.724,34.401 U14.K9@69.975,34.15
PA9: U14.K12 | length 6.3
  Top Layer w0.075: 69.725,29.225 69.725,32.253 69.874,32.402 70.058,32.402 70.207,32.55 70.217,32.55 70.217,33.1 ; 70.225,33.1 70.21,33.115 70.21,33.737 70.372,33.899 71.224,33.899 U14.K12@71.475,34.15
PA10: U14.M15 | length 3.9
  Signal Layer 2 w0.075: 72.725,29.375 72.725,30.753 72.9,30.928 72.9,31.3 72.975,31.375 v2(72.975,33.15)
  other v3: 72.975,33.15
PA11: U14.R9 | length 2.7
  Signal Layer 2 w0.075: v3(69.975,31.65) 69.984,31.641 69.984,31.466 70.05,31.4 70.078,31.4 70.225,31.253 70.225,31.047 70.372,30.901 70.502,30.901 70.503,30.899 70.578,30.899 70.784,30.694 70.784,30.416 70.886,30.314 70.886,29.442
  other v2: 69.975,31.65
PA12: U14.R8 | length 2.5
  Signal Layer 2 w0.075: 68.736,29.55 68.736,31.033 69.01,31.307 69.132,31.307 v3(69.475,31.65)
  other v2: 69.475,31.65
PA13: U14.W9 | length 0.4
  Top Layer w0.075: 69.975,29.275 U14.W9@69.975,29.65
PA14: U14.T8 | length 2.2
  Signal Layer 2 w0.075: 68.893,29.417 68.893,30.527 68.987,30.62 68.987,31.062 69.075,31.15 v3(69.475,31.15)
  other v2: 69.475,31.15
PA15: U14.T10 | length 2
  Signal Layer 2 w0.075: v3(70.475,31.15) 70.682,31.15 70.725,31.106 70.725,31.047 70.944,30.828 70.944,30.606 71.043,30.507 71.043,29.507
  other v2: 70.475,31.15
PB0: U14.B8 | length 0.6
  Signal Layer 2 w0.075: v3(69.475,38.15) 69.475,38.775
  other v2: 69.475,38.15
PB1: U14.D9 | length 1.4
  Signal Layer 1 w0.075: v2(69.975,37.15) 70.225,37.4 70.225,38.4
PB2: U14.E9 | length 1.8
  Signal Layer 1 w0.075: 69.725,38.375 69.725,36.9 v2(69.975,36.65)
PB3: U14.A9 | length 0.5
  Top Layer w0.075: 69.95,39.175 69.975,39.15 U14.A9@69.975,38.65
PB4: U14.C9 | length 1.3
  Signal Layer 2 w0.075: v3(69.975,37.65) 70.01,37.685 70.01,37.81 70.23,38.03 70.23,38.471 70.315,38.555 70.315,38.8
  other v2: 69.975,37.65
PB5: U14.B9 | length 0.9
  Signal Layer 2 w0.075: v3(69.975,38.15) 69.975,39.075
  other v2: 69.975,38.15
PB6: U14.C8 | length 1.5
  Signal Layer 2 w0.075: 69.225,38.998 69.225,38.012 69.44,37.797 69.44,37.685 v3(69.475,37.65)
  other v2: 69.475,37.65
PB7: U14.D7 | length 3.1
  Top Layer w0.075: 67.226,39.079 67.226,38.547 67.25,38.522 67.25,38.5 67.351,38.399 67.578,38.399 67.726,38.252 67.726,38.047 67.873,37.9 68.078,37.9 68.225,37.752 68.225,37.547 68.373,37.399 68.578,37.399 68.798,37.18 68.945,37.18 U14.D7@68.975,37.15
PB8: U14.A7 | length 0.5
  Top Layer w0.075: U14.A7@68.975,38.65 68.975,39.15
PB9: U14.A8 | length 0.5
  Top Layer w0.075: U14.A8@69.475,38.65 69.475,39.175
PB10: U14.E12 | length 2.8
  Top Layer w0.075: U14.E12@71.475,36.65 71.724,36.9 71.724,39.324
PB11: U14.B7 | length 1.1
  Top Layer w0.075: 68.8,39.15 68.732,39.082 68.732,38.55 68.945,38.337 68.945,38.18 U14.B7@68.975,38.15
PB12: U14.E14 | length 2.9
  Signal Layer 1 w0.075: v2(72.475,36.65) 72.725,36.899 72.725,39.375 72.8,39.45
PB13: U14.G15 | length 3.9
  Top Layer w0.075: U14.G15@72.963,35.67 72.726,35.908 72.726,38.253 72.874,38.401 73.069,38.401 73.217,38.55 73.217,38.65 ; 73.225,38.65 73.225,39.125
PB14: U14.H15 | length 0.2
  Signal Layer 2 w0.075: v2(72.975,35.15) 72.975,35.4
  other v3: 72.975,35.15
PB15: U14.J15 | length 5.2
  Top Layer w0.075: U14.J15@72.975,34.65 73.225,34.9 73.225,36.253 73.373,36.401 73.601,36.401 73.732,36.532 73.732,39.232 73.825,39.325
PC0: U14.V9 | length 0.6
  Signal Layer 2 w0.075: 69.975,29.55 v3(69.975,30.15)
  other v2: 69.975,30.15
PC1: U14.V10 | length 0.6
  Signal Layer 2 w0.075: 70.475,29.6 v3(70.475,30.15)
  other v2: 70.475,30.15
PC2: U14.T9 | length 1.6
  Signal Layer 2 w0.075: 69.725,29.65 69.725,30.75 ; 69.726,30.75 69.726,30.753 69.872,30.899 69.875,30.899 69.954,30.979 69.954,31.129 v3(69.975,31.15)
  other v2: 69.975,31.15
PC3: U14.U4 | length 1.5
  Signal Layer 2 w0.075: 66.725,29.625 66.725,30.253 66.873,30.401 67.078,30.401 67.224,30.547 67.224,30.549 67.304,30.629 67.454,30.629 v3(67.475,30.65)
  other v2: 67.475,30.65
PC4: U14.V3 | length 0.6
  Signal Layer 2 w0.075: 66.975,29.6 v3(66.975,30.15)
  other v2: 66.975,30.15
PC5: U14.T7 | length 2.7
  Top Layer w0.075: 67.725,29.225 67.74,29.241 67.74,29.747 67.891,29.897 68.075,29.897 68.225,30.048 68.225,30.253 68.373,30.401 68.578,30.401 68.741,30.563 68.741,30.747 68.889,30.896 68.889,31.029 68.975,31.114 U14.T7@68.975,31.15
PC6: U14.R7 | length 3.6
  Top Layer w0.075: 67.225,29.125 67.225,29.732 67.391,29.897 67.575,29.897 67.726,30.048 67.726,30.253 67.881,30.409 68.065,30.409 68.222,30.565 68.222,30.75 68.372,30.899 68.577,30.899 68.724,31.047 68.724,31.313 68.906,31.494 68.906,31.539 68.975,31.608 U14.R7@68.975,31.65
PC7: U14.W5 | length 0.4
  Top Layer w0.075: 67.975,29.3 U14.W5@67.975,29.65
PC8: U14.U6 | length 1.1
  Signal Layer 2 w0.075: 68.225,29.7 68.225,30.401 v3(68.475,30.65)
  other v2: 68.475,30.65
PC9: U14.V6 | length 0.6
  Signal Layer 2 w0.075: 68.475,29.6 v3(68.475,30.15)
  other v2: 68.475,30.15
PC10: U14.W6 | length 0.4
  Top Layer w0.075: 68.475,29.275 U14.W6@68.475,29.65
PC11: U14.V5 | length 0.6
  Signal Layer 2 w0.075: 67.975,29.6 v3(67.975,30.15)
  other v2: 67.975,30.15
PC12: U14.V4 | length 0.5
  Signal Layer 2 w0.075: 67.475,29.625 v2(67.475,30.15)
  other v3: 67.475,30.15
PCIE_CLKINTN: U14.V13 | length 0.4
  Signal Layer 2 w0.075: 71.975,29.725 v3(71.975,30.15)
  other v2: 71.975,30.15
PCIE_CLKINTP: U14.U13 | length 1.1
  Signal Layer 2 w0.075: 71.726,29.665 71.726,30.253 71.941,30.469 71.941,30.616 v3(71.975,30.65)
  other v2: 71.975,30.65
PCIE_CLKOUTN: U14.U14 | length 1
  Signal Layer 2 w0.075: 72.225,29.75 72.225,30.4 v3(72.475,30.65)
  other v2: 72.475,30.65
PCIE_CLKOUTP: U14.V14 | length 0.5
  Signal Layer 2 w0.075: 72.45,29.675 72.45,30.125 v3(72.475,30.15)
  other v2: 72.475,30.15
PD0: U14.C11 | length 1.6
  Signal Layer 2 w0.075: v3@70.947,37.678 v3(70.975,37.65) 71.01,37.685 71.01,37.833 71.225,38.047 71.225,39.15
  other v2: 70.975,37.65
PD1: U14.F9 | length 2.7
  Signal Layer 2 w0.075: v3(69.975,36.15) 69.975,37.297 70.226,37.548 70.226,37.792 70.395,37.962 70.395,38.402 70.48,38.487 70.48,38.625
  other v2: 69.975,36.15
PD2: U14.A10 | length 0.5
  Top Layer w0.075: U14.A10@70.475,38.65 70.475,39.125
PD3: U14.D8 | length 1.9
  Signal Layer 2 w0.075: v3(69.475,37.15) 69.726,37.401 69.726,38.996
  other v2: 69.475,37.15
PD4: U14.C12 | length 1
  Signal Layer 2 w0.075: v3(71.475,37.65) 71.51,37.685 71.51,37.772 71.56,37.822 71.56,38.588
  other v2: 71.475,37.65
PD5: U14.B12 | length 1
  Top Layer w0.075: 71.225,39.025 71.225,38.517 71.447,38.294 71.447,38.178 U14.B12@71.475,38.15
PD6: U14.A12 | length 0.5
  Top Layer w0.075: U14.A12@71.475,38.65 71.475,39.125
PD7: U14.D12 | length 1.2
  Signal Layer 2 w0.075: v3(71.475,37.15) 71.726,37.401 71.726,37.546 ; 71.726,37.547 71.726,38.253
  other v2: 71.475,37.15
PD8: U14.E11 | length 1.2
  Signal Layer 3 w0.075: v4(70.975,36.65) 70.975,37.875
  other v2: 70.975,36.65
PD9: U14.C10 | length 1.6
  Signal Layer 2 w0.075: v3@70.44,37.685 v3(70.475,37.65) 70.51,37.685 70.51,37.812 70.56,37.863 70.56,38.334 70.645,38.418 70.645,39.093
  other v2: 70.475,37.65
PD10: U14.D11 | length 2
  Signal Layer 2 w0.075: 70.81,39.025 70.81,38.35 70.725,38.266 70.725,37.547 70.94,37.333 70.94,37.185 v3(70.975,37.15)
  other v2: 70.975,37.15
PD11: U14.B10 | length 1.2
  Top Layer w0.075: 70.225,39.225 70.225,38.557 70.452,38.33 70.452,38.173 U14.B10@70.475,38.15
PD12: U14.H14 | length 2.8
  Signal Layer 3 w0.075: 72.315,37.86 72.315,35.594 72.466,35.443 72.466,35.159 v4(72.475,35.15)
  other v2: 72.475,35.15
PD13: U14.G9 | length 4.3
  Top Layer w0.075: 69.175,39.15 69.226,39.1 69.226,38.047 69.372,37.9 69.578,37.9 69.724,37.753 69.724,37.548 69.872,37.401 70.077,37.401 70.225,37.253 70.225,36.047 69.987,35.809 69.987,35.662 U14.G9@69.975,35.65
PE0: U14.B13 | length 1
  Signal Layer 2 w0.075: v3(71.975,38.15) 71.975,39.175
  other v2: 71.975,38.15
PE1: U14.C13 | length 1.6
  Signal Layer 2 w0.075: v3(71.975,37.65) 72.01,37.685 72.01,37.833 72.225,38.047 72.225,39.1
  other v2: 71.975,37.65
PE2: U14.A14 | length 0.6
  Top Layer w0.075: 72.45,39.225 72.475,39.2 U14.A14@72.475,38.65
PE3: U14.A15 | length 0.5
  Top Layer w0.075: U14.A15@72.975,38.65 72.975,39.175
PE4: U14.B14 | length 1.4
  Top Layer w0.075: U14.B14@72.475,38.15 72.475,38.364 72.519,38.407 72.575,38.407 72.717,38.55 72.717,39.383 72.7,39.4
PE5: U14.C14 | length 1.6
  Signal Layer 2 w0.075: v3(72.475,37.65) 72.475,37.7 72.56,37.785 72.56,38.743 72.562,38.746 72.562,39.19
  other v2: 72.475,37.65
PF0: U14.N9 | length 3.9
  Top Layer w0.075: 69.2,29.325 69.226,29.351 69.226,30.7 ; 69.21,30.7 69.21,32.237 69.372,32.399 69.585,32.399 69.819,32.634 69.959,32.634 U14.N9@69.975,32.65
PF1: U14.U8 | length 1.5
  Signal Layer 2 w0.075: 69.226,29.301 69.226,30.253 69.452,30.48 69.452,30.627 v3(69.475,30.65)
  other v2: 69.475,30.65
PF2: U14.P9 | length 3.2
  Signal Layer 2 w0.075: 69.05,29.425 69.05,30.3 69.144,30.393 69.144,30.671 69.372,30.9 69.578,30.9 69.724,31.047 69.724,31.199 69.726,31.2 69.726,31.486 69.726,31.901 v3(69.975,32.15)
  other v2: 69.975,32.15
PF3: U14.W10 | length 0.5
  Top Layer w0.075: U14.W10@70.475,29.65 70.5,29.625 70.5,29.175
PF4: U14.W7 | length 0.3
  Top Layer w0.075: 68.975,29.35 U14.W7@68.975,29.65
PF5: U14.P7 | length 4.9
  Top Layer w0.075: 66.2,29.125 66.2,29.416 66.224,29.44 66.224,29.731 66.391,29.897 66.575,29.897 66.725,30.048 66.725,30.253 66.873,30.401 67.078,30.401 67.225,30.547 67.225,30.753 67.372,30.899 67.66,30.899 67.662,30.897 68.074,30.897 68.224,31.047 68.224,31.252 68.372,31.4 68.577,31.4 68.741,31.563 68.741,31.747 68.964,31.971 68.964,32.139 U14.P7@68.975,32.15
PF6: U14.U5 | length 2.3
  Top Layer w0.075: 66.725,29.15 66.74,29.165 66.74,29.747 66.891,29.897 67.075,29.897 67.225,30.047 67.225,30.253 67.372,30.4 67.578,30.4 67.816,30.638 67.963,30.638 U14.U5@67.975,30.65
PF7: U14.V7 | length 1
  Top Layer w0.075: 68.7,29.25 68.732,29.282 68.732,29.75 68.875,29.893 68.918,29.893 68.975,29.95 U14.V7@68.975,30.15
PF8: U14.U7 | length 1.8
  Top Layer w0.075: 68.2,29.275 68.232,29.307 68.232,29.75 68.383,29.901 68.578,29.901 68.732,30.055 68.732,30.25 68.875,30.393 68.889,30.393 68.975,30.479 U14.U7@68.975,30.65
PF9: U14.T6 | length 1.8
  Signal Layer 2 w0.075: 67.725,29.65 67.725,30.253 67.891,30.418 67.891,30.566 v3(68.475,31.15)
  other v2: 68.475,31.15
PF10: U14.L9 | length 5.1
  Top Layer w0.075: 65.675,32.4 66.578,32.4 66.725,32.548 66.725,32.753 66.872,32.9 67.078,32.9 67.225,33.047 67.225,33.253 67.373,33.4 69.725,33.4 U14.L9@69.975,33.65
PF11: U14.T4 | length 1.8
  Signal Layer 2 w0.075: 65.95,30.4 66.175,30.625 66.536,30.625 66.75,30.839 66.811,30.839 66.873,30.901 67.226,30.901 v3(67.475,31.15)
  other v2: 67.475,31.15
PF12: U14.L7 | length 4.2
  Top Layer w0.075: 64.875,33.9 68.578,33.9 68.628,33.85 68.775,33.85 U14.L7@68.975,33.65
PF13: U14.H2 | length 1.2
  Top Layer w0.075: 65.4,35.4 66.225,35.4 U14.H2@66.475,35.15
PF14: U14.G7 | length 5.1
  Top Layer w0.075: 65.625,38.425 65.839,38.425 65.863,38.4 66.077,38.4 66.226,38.252 66.226,38.047 66.373,37.9 66.578,37.9 66.725,37.753 66.725,37.547 66.872,37.4 67.078,37.4 67.225,37.253 67.225,37.047 67.372,36.901 67.577,36.901 67.725,36.753 67.725,36.547 67.872,36.4 68.078,36.4 68.224,36.253 68.224,36.048 68.372,35.9 68.577,35.9 68.653,35.825 68.8,35.825 68.95,35.675 U14.G7@69,35.675
PF15: U14.G5 | length 1
  Signal Layer 3 w0.075: 66.967,35.65 v4(67.975,35.65)
  other v2: 67.975,35.65
PG0: U14.T5 | length 2
  Signal Layer 2 w0.075: 67.226,29.601 67.226,30.253 67.373,30.401 67.578,30.401 67.726,30.548 67.726,30.901 v3(67.975,31.15)
  other v2: 67.975,31.15
PG1: U14.R4 | length 1.8
  Signal Layer 2 w0.075: 65.799,31.401 67.226,31.401 v3(67.475,31.65)
  other v2: 67.475,31.65
PG2: U14.M7 | length 7
  Top Layer w0.075: 64.75,29.159 64.75,30.458 65.692,31.4 66.557,31.4 66.725,31.568 66.725,31.764 ; 66.736,31.764 66.736,31.786 66.851,31.901 67.078,31.901 67.225,32.048 67.225,32.253 67.372,32.4 68.078,32.4 68.225,32.547 68.225,32.753 68.372,32.899 68.58,32.899 68.816,33.135 68.96,33.135 U14.M7@68.975,33.15
PG3: U14.H12 | length 4.9
  Top Layer w0.075: U14.H12@71.475,35.15 71.726,35.401 72.078,35.401 72.224,35.547 72.224,39.524 72.25,39.55
PG4: U14.N7 | length 5.8
  Top Layer w0.075: 65.9,29.175 65.9,29.372 65.725,29.547 65.725,29.753 65.872,29.899 66.056,29.899 66.107,29.951 66.199,29.951 66.229,29.981 66.229,30.043 66.226,30.047 66.226,30.253 66.382,30.409 66.566,30.409 66.722,30.566 66.722,30.75 66.872,30.9 67.078,30.9 67.225,31.047 67.225,31.253 67.372,31.4 67.637,31.4 67.64,31.397 67.828,31.397 67.831,31.4 68.077,31.4 68.225,31.547 68.225,31.753 68.372,31.899 68.577,31.899 68.724,32.047 68.724,32.313 68.889,32.478 68.889,32.529 68.975,32.614 U14.N7@68.975,32.65
PG5: U14.K1 | length 0.8
  Top Layer w0.075: 65.15,34.15 U14.K1@65.975,34.15
PG6: U14.K2 | length 1.3
  Top Layer w0.075: 65.282,34.393 66.232,34.393 U14.K2@66.475,34.15
PG7: U14.E7 | length 3.8
  Top Layer w0.075: 66.725,38.962 66.725,38.547 66.872,38.4 66.874,38.4 66.875,38.399 67.078,38.399 67.224,38.253 67.224,38.048 67.372,37.901 67.577,37.901 67.725,37.752 67.725,37.547 67.872,37.4 68.078,37.4 68.225,37.253 68.225,37.047 68.372,36.901 68.577,36.901 68.678,36.8 68.825,36.8 U14.E7@68.975,36.65 U14.E7@69,36.65
PG8: U14.E5 | length 1.6
  Signal Layer 3 w0.075: 66.614,36.083 67.408,36.083 v4(67.975,36.65)
  other v2: 67.975,36.65
PG9: U14.G2 | length 1.2
  Top Layer w0.075: 65.375,35.925 65.407,35.893 66.075,35.893 66.218,35.75 66.218,35.707 66.25,35.675 66.275,35.65 U14.G2@66.475,35.65
PG10: U14.F5 | length 1.5
  Signal Layer 3 w0.075: 66.565,35.868 67.647,35.868 67.928,36.15 v4(67.975,36.15)
  other v2: 67.975,36.15
PG11: U14.F7 | length 4.8
  Top Layer w0.075: 66.226,39.117 66.226,38.753 66.226,38.547 66.372,38.4 66.55,38.4 66.551,38.399 66.578,38.399 66.724,38.253 66.724,38.226 ; U14.F7@68.975,36.15 68.787,36.337 68.64,36.337 68.577,36.401 68.372,36.401 68.225,36.547 68.225,36.753 68.078,36.9 67.872,36.9 67.725,37.047 67.725,37.252 67.577,37.401 67.372,37.401 67.225,37.547 67.225,37.753 67.077,37.901 66.872,37.901 66.726,38.047 66.726,38.225 ; 66.724,38.226 66.726,38.225
PG12: U14.H7 | length 4.9
  Top Layer w0.075: 65.85,37.9 66.076,37.9 66.224,37.752 66.224,37.548 66.372,37.4 66.578,37.4 66.725,37.253 66.725,37.047 66.872,36.9 67.078,36.9 67.225,36.753 67.225,36.547 67.372,36.401 67.577,36.401 67.725,36.252 67.725,36.047 67.872,35.9 68.078,35.9 68.225,35.753 68.225,35.547 68.372,35.401 68.724,35.401 U14.H7@68.975,35.15
PG13: U14.J7 | length 5
  Top Layer w0.075: 65.7,37.4 65.871,37.4 65.872,37.399 66.078,37.399 66.225,37.252 66.225,37.047 66.373,36.9 66.578,36.9 66.725,36.753 66.725,36.547 66.872,36.4 67.078,36.4 67.225,36.252 67.225,36.047 67.372,35.9 67.578,35.9 67.726,35.752 67.726,35.547 67.872,35.4 68.078,35.4 68.225,35.253 68.225,35.047 68.372,34.901 68.577,34.901 68.724,34.753 68.724,34.701 68.775,34.65 U14.J7@68.975,34.65
PG14: U14.H5 | length 3.6
  Top Layer w0.075: 65.55,36.925 65.576,36.899 66.078,36.899 66.225,36.753 66.225,36.547 66.372,36.4 66.578,36.4 66.725,36.253 66.725,36.047 66.872,35.9 67.078,35.9 67.225,35.753 67.225,35.546 67.372,35.4 67.578,35.4 67.725,35.253 67.725,35.194 67.768,35.15 U14.H5@67.975,35.15
PG15: U14.E4 | length 1.2
  Signal Layer 3 w0.075: 66.475,36.25 67.075,36.25 v4(67.475,36.65)
  other v2: 67.475,36.65
PH2: U14.L14 | length 3.1
  Signal Layer 3 w0.075: v4(72.475,33.65) 72.975,33.15 72.975,30.78
  other v2: 72.475,33.65
PH3: U14.K14 | length 2.3
  Signal Layer 3 w0.075: v4(72.475,34.15) 72.475,34.159 72.875,34.559 72.875,35.425 73.2,35.75 73.625,35.75
  other v2: 72.475,34.15
PH4: U14.G12 | length 4
  Top Layer w0.075: 70.725,39.225 70.725,38.047 70.873,37.9 71.078,37.9 71.226,37.752 71.226,35.899 U14.G12@71.475,35.65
